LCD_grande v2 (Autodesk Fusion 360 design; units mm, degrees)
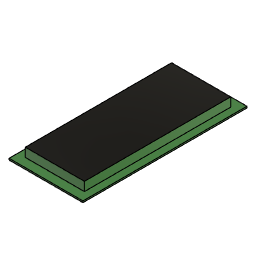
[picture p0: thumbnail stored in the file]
sketch "Boceto" plane through (0, 0, 0) normal (0, 0, 1) x axis (1, 0, 0)
  line L1 (-15.2, 69) -> (34.8, 69)
  line L2 (-15.2, -42) -> (-15.2, 69)
  line L3 (34.8, -42) -> (-15.2, -42)
  line L4 (34.8, 69) -> (34.8, -42)
  line L5 (-15.2, -42) -> (34.8, 69)
  line L6 (34.8, -42) -> (-15.2, 69)
  point P6 (9.8, 13.5)
  point P4 (-15.2, -42)
  point P5 (34.8, -42)
  point P3 (-15.2, 69)
  horizontal L1
  perpendicular L1 L2
  parallel L1 L3
  parallel L2 L4
  coincident L5 P6
  coincident L6 P6
  dimension "d9" distance P4 P5 = 50
  dimension "d10" distance P3 P4 = 111
extrude "Extruir" new body sketch "Boceto" profile of L1 L2 L3 L4 along normal blind 1
sketch "Sketch6" plane through (0, 0, 1) normal (0, 0, 1) x axis (-1, 0, 0)
  line L1 (-34.8, -69) -> (-34.8, 42)
  line L2 (15.2, -69) -> (-34.8, -69)
  line L3 (15.2, 42) -> (15.2, -69)
  line L4 (-34.8, 42) -> (15.2, 42)
  line L5 (-29.8, 36) -> (10.2, 36)
  line L6 (-29.8, -63) -> (-29.8, 36)
  line L7 (10.2, -63) -> (-29.8, -63)
  line L8 (10.2, 36) -> (10.2, -63)
  line L9 (-29.8, -63) -> (10.2, 36)
  line L10 (10.2, -63) -> (-29.8, 36)
  point P10 (-9.8, -13.5)
  point P8 (-29.8, -63)
  point P9 (10.2, -63)
  point P7 (-29.8, 36)
  horizontal L5
  perpendicular L5 L6
  parallel L5 L7
  parallel L6 L8
  coincident L9 P10
  coincident L10 P10
  dimension "d15" distance P8 P9 = 40
  dimension "d16" distance P7 P8 = 99
extrude "Extrude8" new body sketch "Sketch6" profile of L5 L6 L7 L8 along normal blind 6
